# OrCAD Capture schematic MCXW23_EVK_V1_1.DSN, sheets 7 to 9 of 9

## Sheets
7 07_Current_Measurement: size A2
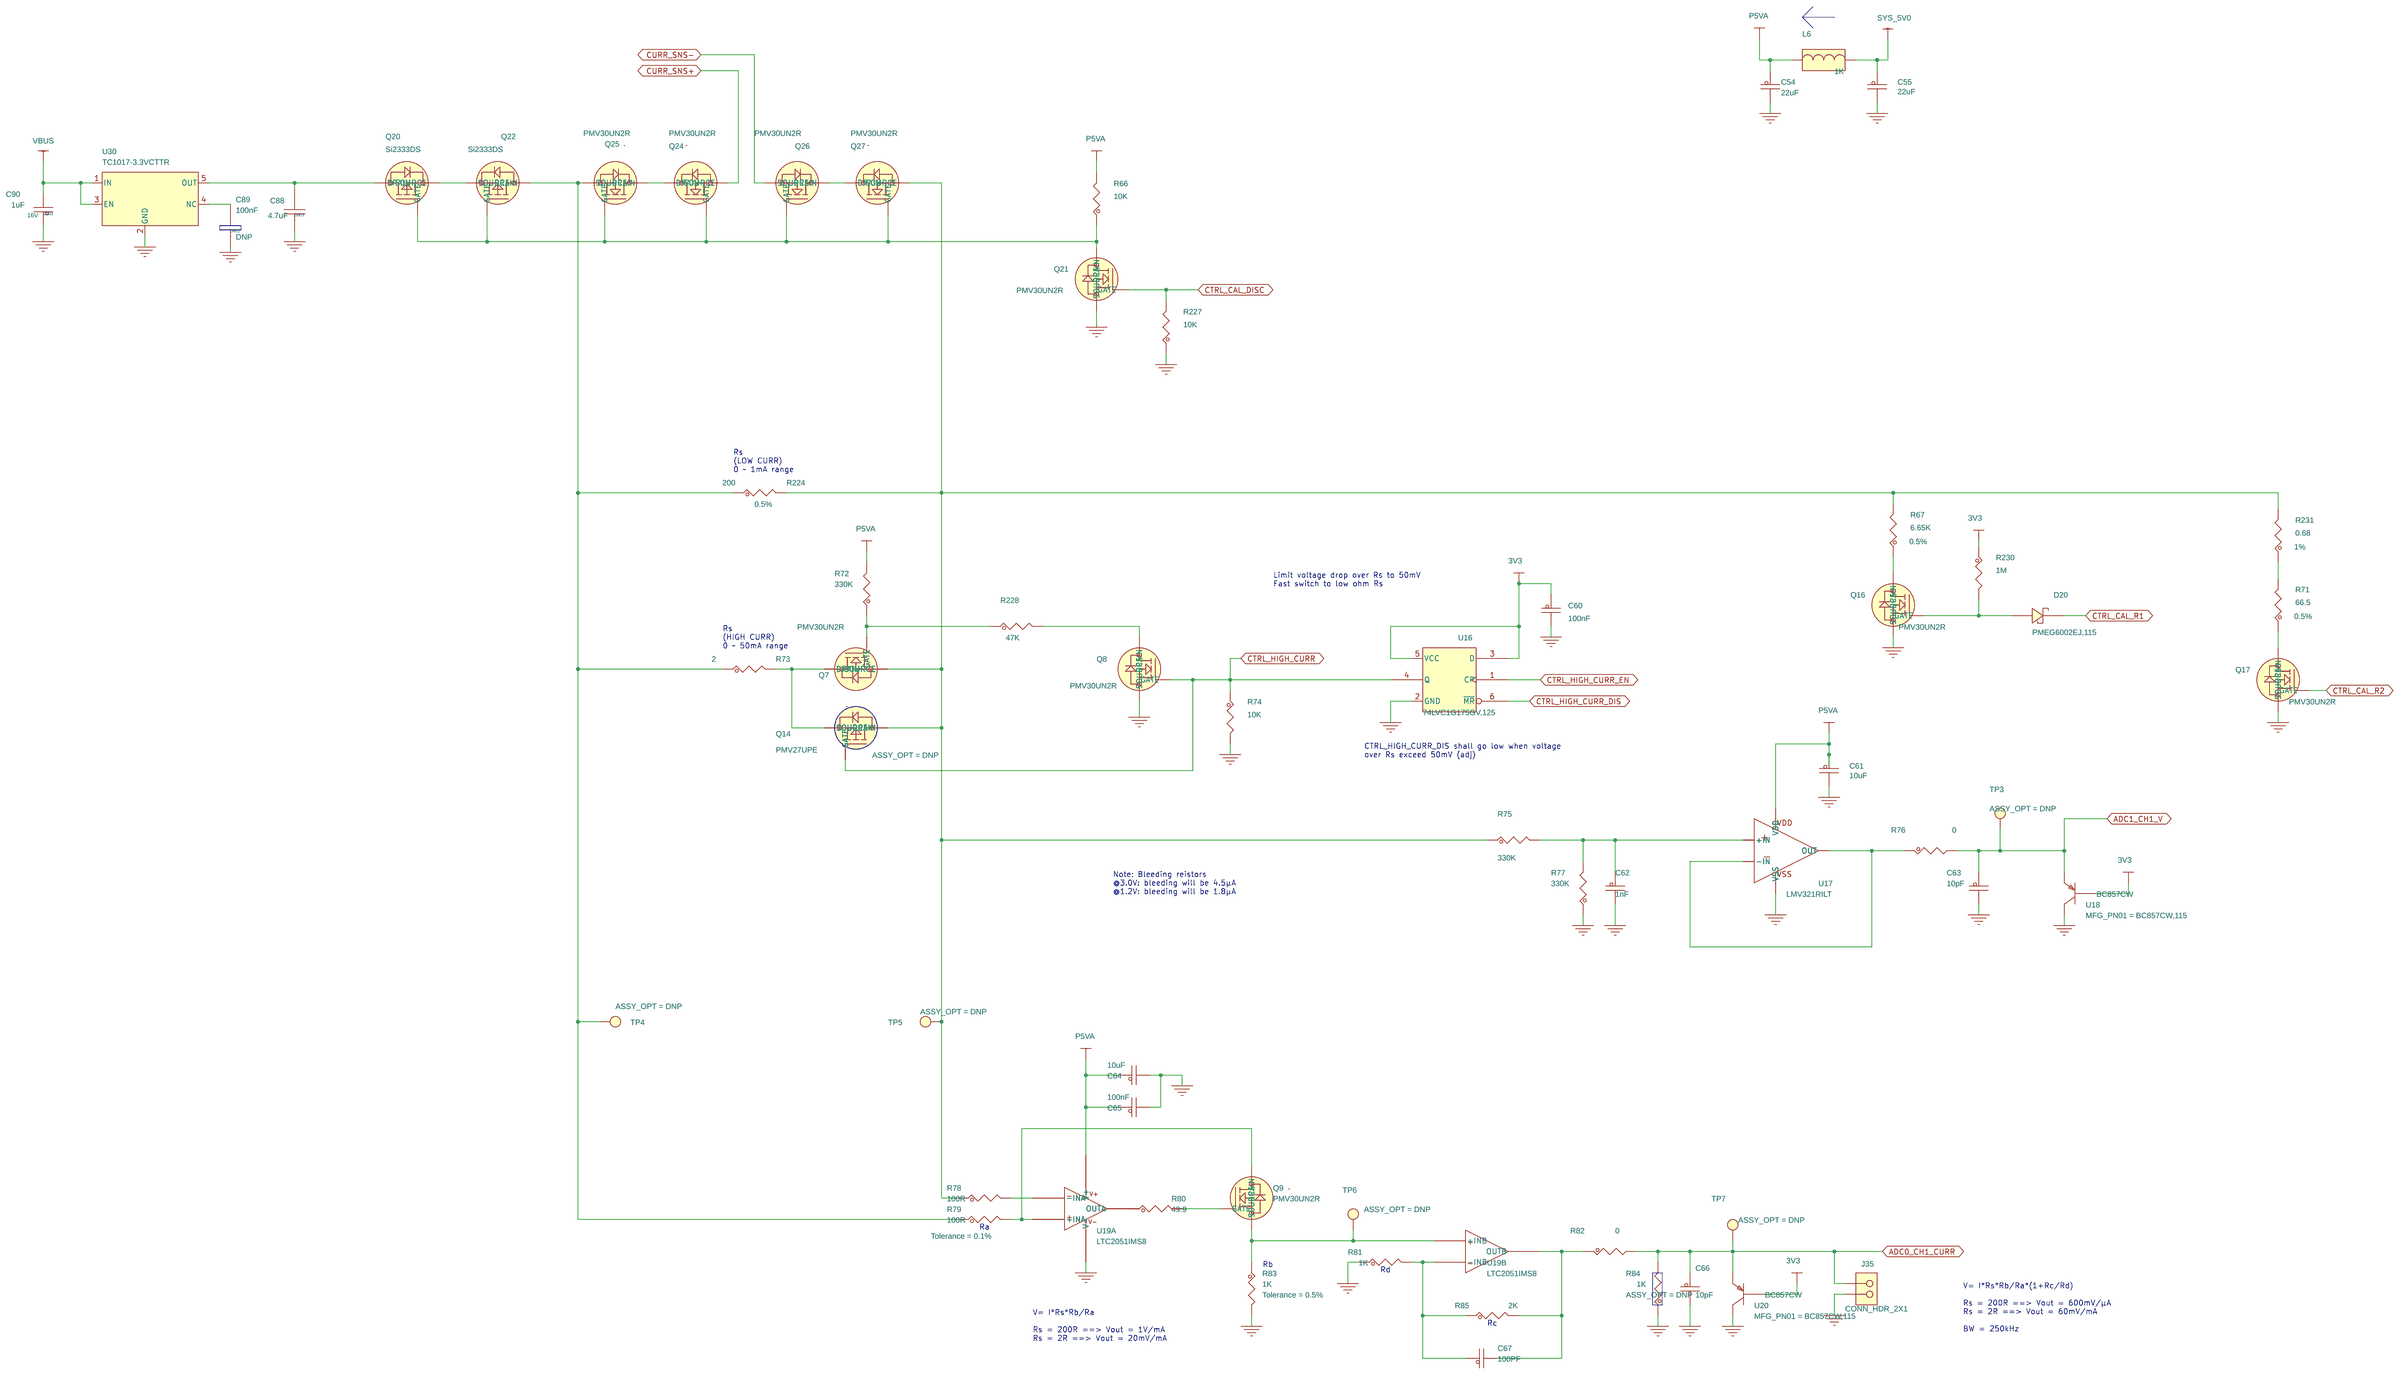
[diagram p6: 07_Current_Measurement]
8 08_MCU Link ISP: size A3
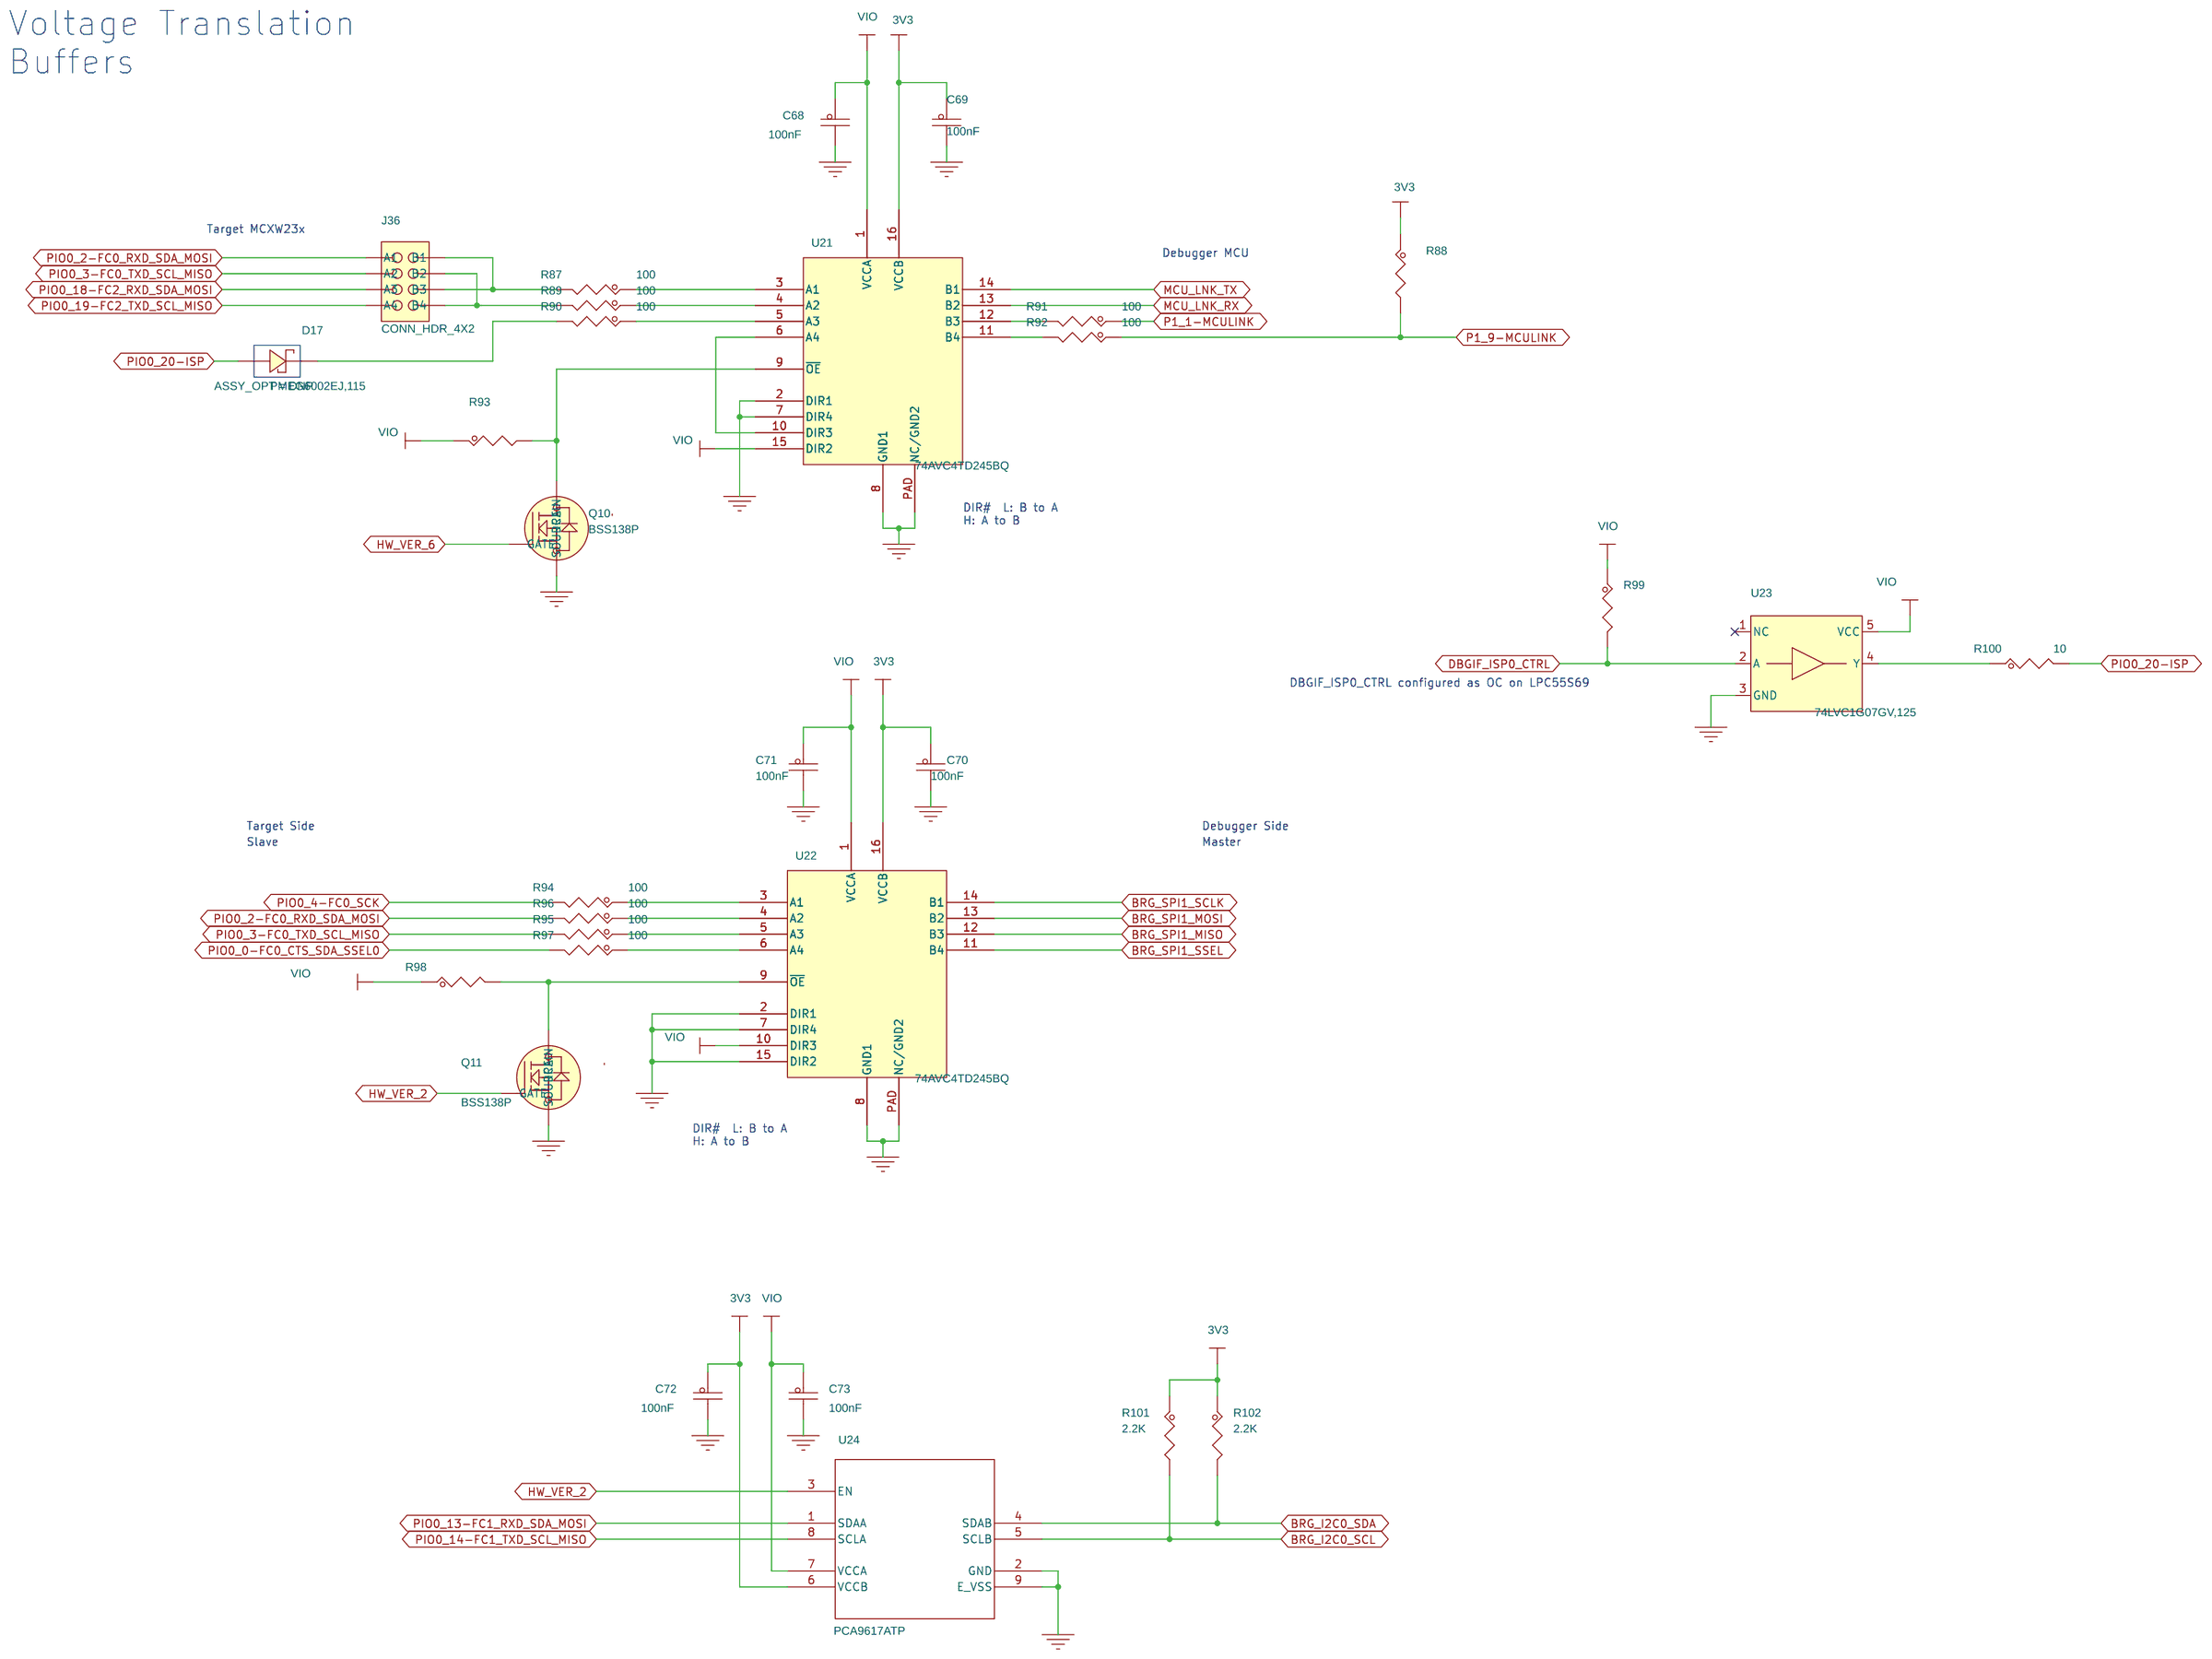
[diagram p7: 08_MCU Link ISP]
9 09_MCU Link SWD: size A3
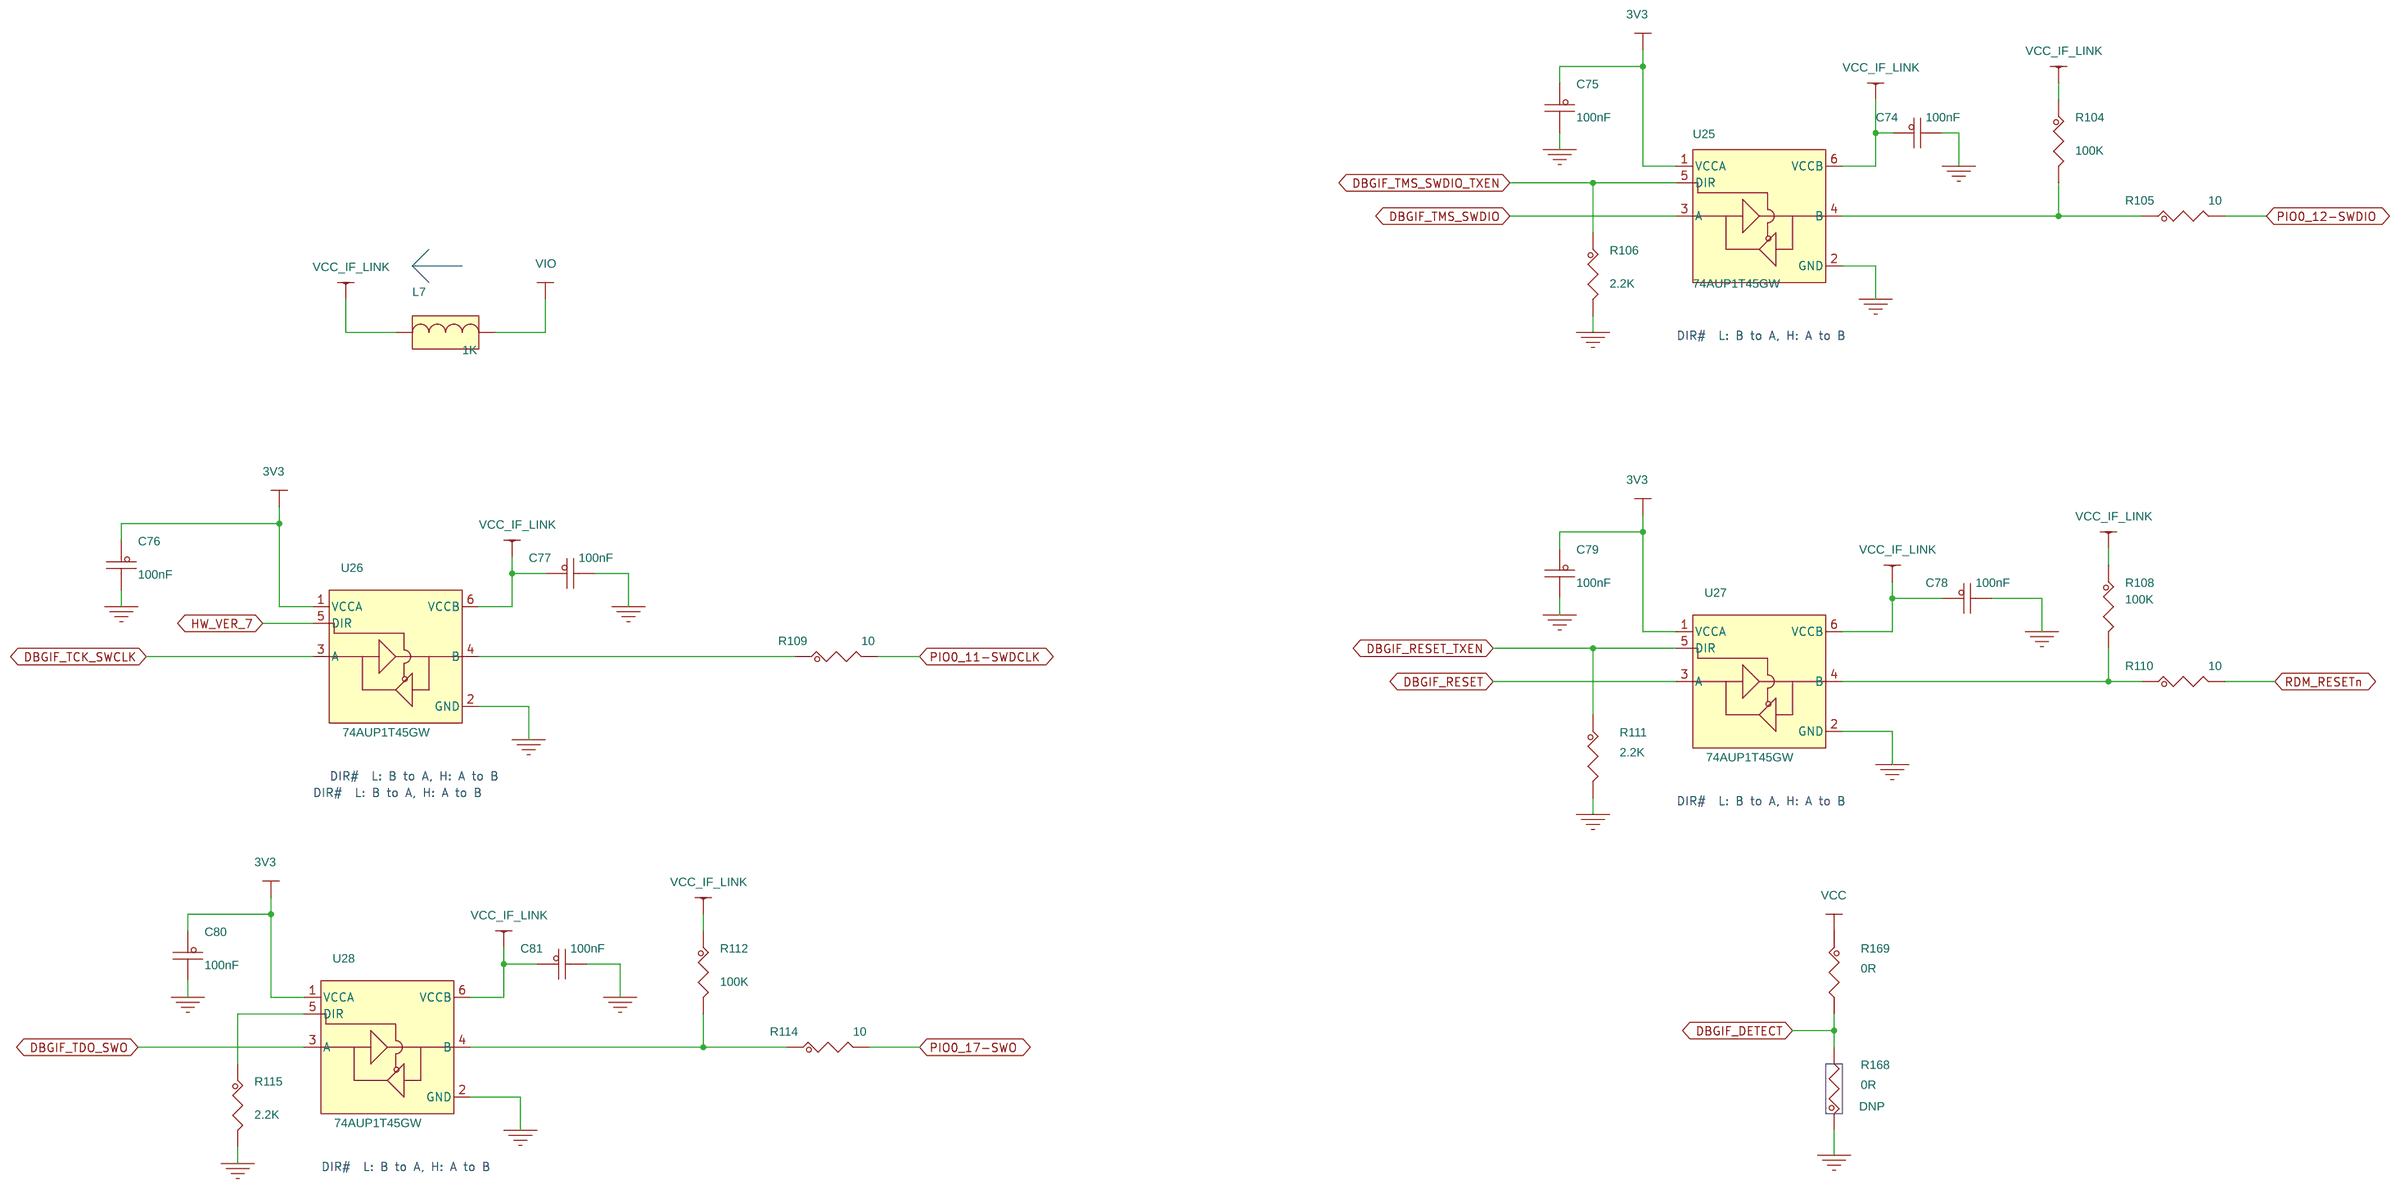
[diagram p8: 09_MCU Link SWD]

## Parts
sheet 07_Current_Measurement
C54  22uF  [CC0603_OV]
C55  22uF  [CC0603_OV]
C60  100nF  [CC0402_25]
C61  10uF  [CC0603_OV]
C62  1nF  [CC0402_25]
C63  10pF  [CC0402_25]
C64  10uF  [CC0603_OV]
C65  100nF  [CC0402_25]
C66  10pF  [CC0402_25]
C67  100PF  [CC0603_OV]
C88  4.7uF  [CC0603_OV]
C89  100nF  [CC0402_25]
C90  1uF  [CC0603_OV]
D20  PMEG6002EJ,115  [SOD323F-R]
J35  CONN_HDR_2X1  [HE14-2X1PTS-MD]
L6  1K  [murata-blm15]
Q7  PMV30UN2R  [SOT23_GSD]
Q8  PMV30UN2R  [SOT23_GSD]
Q9  PMV30UN2R  [SOT23_GSD]
Q14  PMV27UPE  [SOT23_GSD]
Q16  PMV30UN2R  [SOT23_GSD]
Q17  PMV30UN2R  [SOT23_GSD]
Q20  Si2333DS  [SOT23_GSD]
Q21  PMV30UN2R  [SOT23_GSD]
Q22  Si2333DS  [SOT23_GSD]
Q24  PMV30UN2R  [SOT23_GSD]
Q25  PMV30UN2R  [SOT23_GSD]
Q26  PMV30UN2R  [SOT23_GSD]
Q27  PMV30UN2R  [SOT23_GSD]
R66  10K  [RC0402_25]
R67  6.65K  [RC0603_OV]
R71  66.5  [RC0603_OV]
R72  330K  [RC0402_25]
R73  2  [RC0603_OV]
R74  10K  [RC0402_25]
R75  330K  [RC0402_25]
R76  0  [RC0603_OV]
R77  330K  [RC0402_25]
R78  100R  [RC0402_25]
R79  100R  [RC0402_25]
R80  49.9  [RC0402_25]
R81  1K  [RC0402_25]
R82  0  [RC0603_OV]
R83  1K  [RC0402_25]
R84  1K  [RC0402_25]
R85  2K  [RC0603_OV]
R224  200  [RC0603_OV]
R227  10K  [RC0402_25]
R228  47K  [RC0402_25]
R230  1M  [RC0402_25]
R231  0.68  [RC0603_OV]
TP3  TPAD_050  [TPAD_050]
TP4  TPAD_050  [TPAD_050]
TP5  TPAD_050  [TPAD_050]
TP6  TPAD_050  [TPAD_050]
TP7  TPAD_050  [TPAD_050]
U16  74LVC1G175GV,125  [SOT457]
U17  LMV321RILT  [sot23-5-R]
U18  BC857CW  [SC70-BEC]
U19  LTC2051IMS8  [MSOP8_MS]  (sections A,B)
U20  BC857CW  [SC70-BEC]
U30  TC1017-3.3VCTTR  [SOT23-5-R]
sheet 08_MCU Link ISP
C68  100nF  [CC0402_25]
C69  100nF  [CC0402_25]
C70  100nF  [CC0402_25]
C71  100nF  [CC0402_25]
C72  100nF  [CC0402_25]
C73  100nF  [CC0402_25]
D17  PMEG6002EJ,115  [SOD323F-R]
J36  CONN_HDR_4X2  [HE14-2X4PTS-MD]
Q10  BSS138P  [SOT23_GSD]
Q11  BSS138P  [SOT23_GSD]
R87  100  [RC0402_25]
R88  10K  [RC0402_25]
R89  100  [RC0402_25]
R90  100  [RC0402_25]
R91  100  [RC0402_25]
R92  100  [RC0402_25]
R93  10K  [RC0402_25]
R94  100  [RC0402_25]
R95  100  [RC0402_25]
R96  100  [RC0402_25]
R97  100  [RC0402_25]
R98  10K  [RC0402_25]
R99  10K  [RC0402_25]
R100  10  [RC0402_25]
R101  2.2K  [RC0402_25]
R102  2.2K  [RC0402_25]
U21  74AVC4TD245BQ  [DHVQFN16]
U22  74AVC4TD245BQ  [DHVQFN16]
U23  74LVC1G07GV,125  [SOT753]
U24  PCA9617ATP  [HWSON8]
sheet 09_MCU Link SWD
C74  100nF  [CC0402_25]
C75  100nF  [CC0402_25]
C76  100nF  [CC0402_25]
C77  100nF  [CC0402_25]
C78  100nF  [CC0402_25]
C79  100nF  [CC0402_25]
C80  100nF  [CC0402_25]
C81  100nF  [CC0402_25]
L7  1K  [murata-blm15]
R104  100K  [RC0402_25]
R105  10  [RC0402_25]
R106  2.2K  [RC0402_25]
R108  100K  [RC0402_25]
R109  10  [RC0402_25]
R110  10  [RC0402_25]
R111  2.2K  [RC0402_25]
R112  100K  [RC0402_25]
R114  10  [RC0402_25]
R115  2.2K  [RC0402_25]
R168  0R  [RC0603_OV]
R169  0R  [RC0603_OV]
U25  74AUP1T45GW  [sot363]
U26  74AUP1T45GW  [sot363]
U27  74AUP1T45GW  [sot363]
U28  74AUP1T45GW  [sot363]

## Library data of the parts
C54 C55 = CAP_NP: CAP CER 22uF 10V 20% X5R 0603; AGILE_PN: 150-79530; CAD_APPROVED: Yes; FPLIST: CC0603_OV,CC0603; HEIGHT: 1MM; MFG_NAME01: TDK; MFG_PN01: C1608X5R1A226M080AC; Manufacturer: TDK; Manufacturer PN: C1608X5R1A226M080AC; Package Size: 0603; ROHS: Yes; Tolerance: 20%; VOLTAGE: 10V
C60 C65 C68-C73 C75-C81 = CAP_NP: CAP CER 0.1UF 25V X7R 0402; FPLIST: CC0402_25,CC0402_HD,0402_CC; HEIGHT: 0.55MM; MFG_NAME01: TDK; MFG_PN01: CGA2B3X7R1E104K050BB; Manufacturer: TDK; Manufacturer PN: CGA2B3X7R1E104K050BB; Package Size: 0402; Package Type: SMD; ROHS: Yes; TYPE: 0402; Tolerance: 10%; VOLTAGE: 25V
C61 C64 = CAP_NP: SMD Multilayer Ceramic Capacitor, 10 µF, 10 V, 0603, ± 20%, X5R; CAD_APPROVED: Yes; FPLIST: CC0603_OV,CC0603; Farnell: 2113070; HEIGHT: 1MM; MFG_NAME01: Taiyo Yuden; MFG_PN01: LMK107BBJ106MALT; Manufacturer: Taiyo Yuden; Manufacturer PN: LMK107BBJ106MALT; Package Size: 0603; ROHS: Yes; Tolerance: 20%; VOLTAGE: 10V
C62 = CAP_NP: CAP CER 0.001uF 50V 10% X7R 0402; AGILE_PN: 150-80278; CAD_APPROVED: Yes; FPLIST: CC0402_25,CC0402_HD,0402_CC; HEIGHT: 0.6MM; MFG_NAME01: VISHAY INTERTECHNOLOGY; MFG_PN01: VJ0402Y102KXAAC; Manufacturer: VISHAY INTERTECHNOLOGY; Manufacturer PN: VJ0402Y102KXAAC; Package Size: 0402; Package Type: SMD; ROHS: Yes; Temp Range: -55°C to +150°C; Tolerance: 10%; VOLTAGE: 50V
C63 C66 = CAP_NP: CAP CER 10pF 50V 2% C0G 0402; AGILE_PN: 150-78893; CAD_APPROVED: Yes; FPLIST: CC0402_25,CC0402_HD,0402_CC; HEIGHT: 0.55 MM; MFG_NAME01: MURATA; MFG_PN01: GJM1555C1H100GB01D; Manufacturer: MURATA; Manufacturer PN: GJM1555C1H100GB01D; Package Size: 0402; Package Type: 180mm Paper Tape; ROHS: Yes; Temp Range: -55°C to +125°C; Tolerance: 2%; VOLTAGE: 50V
C67 = CAP_NP: CAP CER 100pF 100V 5% C0G 0603; AGILE_PN: 150-80505; CAD_APPROVED: Yes; FPLIST: CC0603_OV,CC0603,0603_CC; HEIGHT: 0.87MM; MFG_NAME01: WURTH ELEKTRONIK EISOS GMBH & CO. KG (ELECTRONIC & ELECTROMEHANICAL COMP); MFG_PN01: 885012006079; Manufacturer: WURTH ELEKTRONIK EISOS GMBH & CO. KG (ELECTRONIC & ELECTROMEHANICAL COMP); Manufacturer PN: 885012006079; ROHS: Yes; Temp Range: -55°C ~ 125°C
C88 = CAPACITOR__0: SMD Multilayer Ceramic Capacitor, 4.7 µF, 16 V, ± 10%, X5R; CAD_APPROVED: Yes; CLASS: DISCRETE; FPLIST: CC0603_OV,CC0603; Farnell: 3581438; HEIGHT: 1MM; MFG_NAME01: MURATA; MFG_PN01: GRT188R61C475KE13D; Manufacturer: MURATA; Manufacturer PN: GRT188R61C475KE13D; PUISS/VOLT: 10V; Package Size: 0603; TYPE: 0603; VOLTAGE: 16V
C89 = CAPACITOR__0: CAP CER 0.1UF 25V X7R 0402; ASSY_OPT: DNP; Assembly Option: DNP; CLASS: DISCRETE; FPLIST: CC0402_25,CC0402_HD,0402_CC; HEIGHT: 0.55MM; MFG_NAME01: TDK; MFG_PN01: CGA2B3X7R1E104K050BB; Manufacturer: TDK; Manufacturer PN: CGA2B3X7R1E104K050BB; Package Size: 0402; Package Type: SMD; ROHS: Yes; TOLERANCE: 10%; TYPE: 0402; VOLTAGE: 25V
C90 = CAP_NP: CAP CER 1UF 16V X5R 0603; Distributor: Digi-Key; Distributor PN: 490-1536-6-ND; MFG_NAME01: Murata Electronics North America; MFG_PN01: GRM188R61C105KA93D; Manufacturer: Murata Electronics North America; Manufacturer PN: GRM188R61C105KA93D; OrderCode: FARNELL 1907343; PUISS/VOLT: 16V; STUFFING: YES; Type: 0603; Datasheet: http://www.murata.com/~/media/webrenewal/support/library/catalog/products/capacitor/mlcc/c02e.ashx
D20 = DIODE_SCHTKY: Schottky Rectifier, Low VF, 60 V, 200 mA, Single, SOD-323F, 2 Pins, 600 mV; Farnell: 1972726; MFG_NAME01: Nexperia USA Inc.; Manufacturer: Nexperia USA Inc.; Datasheet: https://assets.nexperia.com/documents/data-sheet/PMEG6002EJ.pdf
J35 = CONN_HDR_2X1
L6 = BEAD: IND FER BEAD 1K@100MHz 250mA 25% 0402; AGILE_PN: 180-78847; CAD_APPROVED: Yes; FPLIST: IND_0402,0402_CC; Farnell: 1515785; HEIGHT: 0.55MM; MFG_NAME01: MURATA; MFG_PN01: BLM15HD102SN1; Manufacturer: MURATA; Manufacturer PN: BLM15HD102SN1; ROHS: Yes; Temp Range: -55&#8451; to 125&#8451;
Q7-Q9 Q16 Q17 Q21 Q24-Q27 = MOSFET_N_0: Power MOSFET, N Channel, 20 V, 5.4 A, 0.024 ohm, SOT-23, Surface Mount; CAD_APPROVED: Yes; Farnell: 2469652; HEIGHT: 3.0MM; MFG_NAME01: NEXPERIA; Manufacturer: NEXPERIA; ROHS: Yes; Temp Range: -65°C ~ 150°C; Temp_Range: -65°C ~ 150°C; VOLTAGE: 20V
Q14 = MOSFET_P_0: TRAN PMOS 20V 4.5A SOT23-3; AGILE_PN: 480-80187; ASSY_OPT: DNP; Assembly Option: DNP; CAD_APPROVED: Yes; HEIGHT: 1.1 MM; MFG_NAME01: Nexperia; MFG_PN01: PMV27UPER; Manufacturer: Nexperia; Manufacturer PN: PMV27UPER; Package Size: 1.4x3x1.1MM; ROHS: Yes; Rated Power: 490mW (Ta), 4.15W (Tc)
Q20 = MOSFET_P_0: MOSFET 12V 5.3A 1.25W 32mohm @ 4.5V; AGILE_PN: 480-80187; CAD_APPROVED: Yes; Farnell: 1867182; HEIGHT: 1.1 MM; MFG_NAME01: Vishay; Manufacturer: Vishay; Mouser: 781-SI2333DS-GE3; Package Size: 1.4x3x1.1MM; ROHS: Yes; Rated Power: 490mW (Ta), 4.15W (Tc)
Q22 = MOSFET_P_0: MOSFET 12V 5.3A 1.25W 32mohm @ 4.5V; AGILE_PN: 480-80187; CAD_APPROVED: Yes; Farnell: 1867182; HEIGHT: 1.1 MM; MFG_NAME01: Vishay; MFG_PN01: PMV27UPER; Manufacturer: Vishay; Manufacturer PN: PMV27UPER; Mouser: 781-SI2333DS-GE3; Package Size: 1.4x3x1.1MM; ROHS: Yes; Rated Power: 490mW (Ta), 4.15W (Tc)
R66 R74 R227 = RES: RES MF 10K 1/16W 1% 0402; AGILE_PN: 470-80452; CAD_APPROVED: Yes; FPLIST: RC0402_25,RC0402_HD,0402_CC; HEIGHT: 0.40 MM; MFG_NAME01: NIC COMPONENTS CORP; MFG_PN01: NRCL04F1002TRF; Manufacturer: NIC COMPONENTS CORP; Manufacturer PN: NRCL04F1002TRF; ROHS: Yes; Tolerance: 1%
R67 = RES: RES MF 6.65K 1/10W 1% AEC-Q200 0603; AGILE_PN: 470-81749; CAD_APPROVED: Yes; Digikey: 311-2659-2-ND; FPLIST: RC0603_OV,RC0603,0603_CC; HEIGHT: 0.55MM; MFG_NAME01: YAGEO; MFG_PN01: RT0603DRE076K65L; Manufacturer: YAGEO; Manufacturer PN: RT0603DRE076K65L; ROHS: Yes; Temp Range: -55C to +155C; Tolerance: 0.5%
R71 = RES: RES SMD 66.5OHM 0.5% 1/10W 0603; CAD_APPROVED: Yes; Digikey: YAG1713CT-ND; FPLIST: RC0603_OV,RC0603,0603_CC; MFG_NAME01: YAGEO; MFG_PN01: RT0603BRD0766R5L; Manufacturer: YAGEO; Manufacturer PN: RT0603BRD0766R5L; ROHS: Yes; Temp Range: -55C to +155C; Tolerance: 0.5%
R72 R75 R77 = RES: RES MF 330K  1/16W 1% 0402; AGILE_PN: 470-31117; CAD_APPROVED: Yes; FPLIST: RC0402_25,RC0402_HD,0402_CC; HEIGHT: 0.40 MM; MFG_NAME01: YAGEO AMERICA; MFG_PN01: RC0402FR-07330KL; Manufacturer: YAGEO AMERICA; Manufacturer PN: RC0402FR-07330KL; ROHS: Yes; Temp Range: -55°C ~ 155°C; Tolerance: 1%; VOLTAGE: 50V
R73 = RES: RES 0603 2R0 0.1% 25PPM 1K RL; AGILE_PN: 470-82171; CAD_APPROVED: Yes; Digikey: 1712-CPF0603B2R0E1CT-ND; FPLIST: RC0603_OV,RC0603,0603_CC; HEIGHT: 0.55MM; MFG_NAME01: ROHM; MFG_PN01: ESR10EZPF2R00; Manufacturer: ROHM; Manufacturer PN: ESR10EZPF2R00; ROHS: Yes; Temp Range: -55°C ~ 155°C; Tolerance: 0.5%
R76 R82 = RES: RES MF ZERO OHM 1/10W -- 0603; AGILE_PN: 470-80866; CAD_APPROVED: Yes; FPLIST: RC0603_OV,RC0603,R603-X2,0603_CC; HEIGHT: 0.6MM; MFG_NAME01: YAGEO AMERICA; MFG_PN01: RC0603FR-070RL; Manufacturer: YAGEO AMERICA; Manufacturer PN: RC0603FR-070RL; ROHS: Yes; Temp Range: –55 °C to +155 °C
R78 R79 = RES: RES MF 100 OHM 1/16W 0.1% AEC-Q200 0402; AGILE_PN: 470-30279; CAD_APPROVED: Yes; FPLIST: RC0402_25,RC0402_HD,0402_CC; HEIGHT: 0.4MM; MFG_NAME01: VISHAY INTERTECHNOLOGY; MFG_PN01: MCS04020D1000BE100; Manufacturer: VISHAY INTERTECHNOLOGY; Manufacturer PN: MCS04020D1000BE100; ROHS: Yes; Tolerance: 0.1%
R80 = RES: RES 49.9 OHM 1/16W 0.1% AEC-Q200 0402; AGILE_PN: 470-76559; CAD_APPROVED: Yes; FPLIST: RC0402_25,RC0402_HD,0402_CC; HEIGHT: 0.4mm; MFG_NAME01: SUSUMU CO. LTD.; MFG_PN01: RG1005P-49R9-B; Manufacturer: SUSUMU CO. LTD.; Manufacturer PN: RG1005P-49R9-B; ROHS: Yes; Tolerance: 0.1%; VOLTAGE: 25V
R81 R83 = RES: RES MF 1K 1/16W 0.5% 0402; AGILE_PN: 470-80057; CAD_APPROVED: Yes; FPLIST: RC0402_25,RC0402_HD,0402_CC; HEIGHT: 0.4MM; MFG_NAME01: PANASONIC; MFG_PN01: ERA2AED102X; Manufacturer: PANASONIC; Manufacturer PN: ERA2AED102X; ROHS: Yes; Tolerance: 0.5%
R84 = RES: RES MF 1K 1/16W 0.5% 0402; AGILE_PN: 470-80057; ASSY_OPT: DNP; Assembly Option: DNP; CAD_APPROVED: Yes; FPLIST: RC0402_25,RC0402_HD,0402_CC; HEIGHT: 0.4MM; MFG_NAME01: PANASONIC; MFG_PN01: ERA2AED102X; Manufacturer: PANASONIC; Manufacturer PN: ERA2AED102X; ROHS: Yes; Tolerance: 0.5%
R85 = RES: RES MF 2K 1/10W 1% 0603; AGILE_PN: 470-81379; CAD_APPROVED: Yes; FPLIST: RC0603_OV,RC0603,0603_CC; HEIGHT: 0.55MM; MFG_NAME01: YAGEO; MFG_PN01: RC0603FR-072KL; Manufacturer: YAGEO; Manufacturer PN: RC0603FR-072KL; ROHS: Yes; Temp Range: -55°C to +155°C; Tolerance: 1%
R224 = RES: RES MF 200 OHM 1/8W 0.5% 0603; AGILE_PN: 470-81343; CAD_APPROVED: Yes; FPLIST: RC0603_OV,RC0603,0603_CC; Farnell: 3579762; HEIGHT: 0.55MM; MFG_NAME01: Panasonic; MFG_PN01: ERJUP3D2000V; Manufacturer: Panasonic; Manufacturer PN: ERJUP3D2000V; ROHS: Yes; Temp Range: -55°C to +155°C; Tolerance: 0.5%
R228 = RES: SMD Chip Resistor, 47 kohm, ± 1%, 62.5 mW, 0402 [1005 Metric], Thick Film, General Purpose; CAD_APPROVED: Yes; FPLIST: RC0402_25,RC0402_HD,0402_CC; HEIGHT: 0.40 MM; MFG_NAME01: YAGEO AMERICA; MFG_PN01: RC0402FR-0747KL; Manufacturer: YAGEO AMERICA; Manufacturer PN: RC0402FR-0747KL; ROHS: Yes; Temp Range: -55°C ~ 155°C; Tolerance: 1%; VOLTAGE: 50V
R230 = RES: RES MF 1M 1/16W 1% 0402; CAD_APPROVED: Yes; FPLIST: RC0402_25,RC0402_HD,0402_CC; HEIGHT: 0.40 MM; MFG_PN01: AC0402FR-071ML; Manufacturer PN: AC0402FR-071ML; ROHS: Yes; Tolerance: 1%
R231 = RES: RES SMD 0.68OHM 1% 1/10W 0603; CAD_APPROVED: Yes; FPLIST: RC0603_OV,RC0603,0603_CC; MFG_NAME01: PANASONIC; MFG_PN01: ERJ3BQFR68V; Manufacturer: PANASONIC; Manufacturer PN: ERJ3BQFR68V; ROHS: Yes; Temp Range: -55C to +155C; Tolerance: 1%
TP3-TP7 = TEST_POINT_L: TEST POINT PAD 50MIL DIA SMT, NO PART TO ORDER; AGILE_PN: 211-76644; ASSY_OPT: DNP; Assembly Option: DNP; CAD_APPROVED: Yes; EN: 666-1-00186; HEIGHT: 0.1MM; KEY Number: 666-1-00186@1; MFG_NAME01: NOTACOMPONENT; MFG_PN01: NOTACOMPONENT; Manufacturer: NOTACOMPONENT; Manufacturer PN: NOTACOMPONENT; Mfg: NA; Mfg Part No: 666-1-00186; ROHS: Yes
U16 = 1_D_FLIPFLOP_6P: IC FLIP-FLOP SINGLE D-TYPE 1.65-5.5V SOT363; AGILE_PN: 312-82400; CAD_APPROVED: YES; Farnell: 2445063; HEIGHT: 1.1 MM; MFG_NAME01: Nexperia USA Inc.; Manufacturer: Nexperia USA Inc.; Package Size: SC-74, SOT-457; ROHS: YES; Supply Voltage: 1.65V ~ 5.5V
U17 = OPAMP_SGL_5P: Operational Amplifier, Single, 1 Amplifier, 1.3 MHz, 0.45 V/µs, 2.7V to 6V, SOT-23, 5 Pins; 3D_Mechanical_Footprint_File: sot23-5; AGILE_PN: 315-81237; CAD_APPROVED: Yes; Farnell: 1374134; HEIGHT: 1.45MM; MFG_NAME01: STMicroelectronics; Manufacturer: STMicroelectronics; ROHS: Yes; Temp Range: -40C to 125C; VOLTAGE: 2.7-6V
U18 U20 = PNP_0: TRAN PNP GEN 100mA 45V AEC-Q101 SC70; AGILE_PN: 480-80464; CAD_APPROVED: YES; Farnell: 1907655; HEIGHT: 1.1 MM; MFG_NAME01: Nexperia USA Inc.; MFG_PN01: BC857CW,115; Manufacturer: Nexperia USA Inc.; Manufacturer PN: BC857CW,115; Package Size: SC-70, SOT-323; ROHS: YES; Rated Power: 200mW; Temp Range: -65°C to +150°C
U19 = OPAMP_DUAL_8P_B: IC LIN OPAMP DUAL 2.7-5.5V MSOP8; AGILE_PN: 315-80868; CAD_APPROVED: Yes; HEIGHT: 1.1MM; MFG_NAME01: ANALOG DEVICES; MFG_PN01: LTC2051IMS8#PBF; Manufacturer: ANALOG DEVICES; Manufacturer PN: LTC2051IMS8#PBF; Mouser: 584-LTC2051IMS8#PBF; Package Size: MSOP-8; ROHS: Yes; VOLTAGE: 2.7-5.5V
U30 = TPS76930_1: Fixed LDO Voltage Regulator, 2.7V to 6V, 285mV Dropout, 3.3Vout, 150mAout, SOT-23-5; Distributor: Digi-Key; Farnell: 1331509; Manufacturer: Microchip; STUFFING: YES; Supplier: Digikey; Datasheet: https://www.farnell.com/datasheets/2124733.pdf
D17 = DIODE_SCHTKY: Schottky Rectifier, Low VF, 60 V, 200 mA, Single, SOD-323F, 2 Pins, 600 mV; ASSY_OPT: DNP; Assembly Option: DNP; Farnell: 1972726; MFG_NAME01: Nexperia USA Inc.; Manufacturer: Nexperia USA Inc.; Datasheet: https://assets.nexperia.com/documents/data-sheet/PMEG6002EJ.pdf
J36 = CONN_HDR_4X2: Pin Header, Board-to-Board, 2.54 mm, 2 Rows, 8 Contacts, Through Hole, AMPMODU II; Farnell: 3398641; MFG_NAME01: AMP - TE CONNECTIVITY; MFG_PN01: 826656-4; Manufacturer: AMP - TE CONNECTIVITY; Manufacturer PN: 826656-4
Q10 Q11 = MOSFET_N_0: TRAN NMOS 60V 360MA AEC-Q101 TO-236AB; AGILE_PN: 480-79842; CAD_APPROVED: Yes; Farnell: 1859849; HEIGHT: 1.1MM; MFG_NAME01: NEXPERIA; MFG_PN01: BSS138P,215; Manufacturer: NEXPERIA; Manufacturer PN: BSS138P,215; ROHS: Yes; Temp Range: -65°C ~ 150°C; Temp_Range: -65°C ~ 150°C; VOLTAGE: 60V
R87 R89-R92 R94-R97 = RES: RES MF 100 OHM 1/16W 5% 0402; AGILE_PN: 470-75591; CAD_APPROVED: Yes; FPLIST: RC0402_25,RC0402_HD,RC0402_X2,0402_CC; HEIGHT: 0.45mm; MFG_NAME01: PANASONIC; MFG_PN01: ERJ2GEJ101X; Manufacturer: PANASONIC; Manufacturer PN: ERJ2GEJ101X; ROHS: Yes; Tolerance: 5%
R88 R93 R98 = RES: RES MF 10K 1/16W 5% 0402; AGILE_PN: 470-75557; CAD_APPROVED: Yes; FPLIST: RC0402_25,RC0402_HD,0402_CC; HEIGHT: 0.4 MM; MFG_NAME01: VISHAY INTERTECHNOLOGY; MFG_PN01: CRCW040210K0JNED; Manufacturer: VISHAY INTERTECHNOLOGY; Manufacturer PN: CRCW040210K0JNED; ROHS: Yes; TOL: 5%; Tolerance: 5%
R99 = RES: RES MF 10K 1/16W 5% 0402; AGILE_PN: 470-75557; CAD_APPROVED: Yes; FPLIST: RC0402_25,RC0402_HD,0402_CC; HEIGHT: 0.4 MM; MFG_NAME01: VISHAY INTERTECHNOLOGY; MFG_PN01: CRCW040210K0JNED; Manufacturer: VISHAY INTERTECHNOLOGY; Manufacturer PN: CRCW040210K0JNED; ROHS: Yes; Tolerance: 5%
R100 R105 R109 R110 R114 = RES: RES MF 10 OHM 1/16W 1% AEC-Q200 0402; AGILE_PN: 470-80978; CAD_APPROVED: Yes; FPLIST: RC0402_25,RC0402_HD,0402_CC; HEIGHT: 0.4MM; MFG_NAME01: KOA SPEER; MFG_PN01: RK73H1ETTP10R0F; Manufacturer: KOA SPEER; Manufacturer PN: RK73H1ETTP10R0F; ROHS: Yes; Temp Range: –55 °C to +155 °C; Tolerance: 1%
R101 R102 R106 R111 R115 = RES: RES MF 2.2K 1/16W 1% 0402; AGILE_PN: 470-78359; CAD_APPROVED: Yes; FPLIST: RC0402_25,RC0402_HD,0402_CC; HEIGHT: 0.4MM; MFG_NAME01: WALSIN TECHNOLOGY CORP.; MFG_PN01: WR04X2201FTL; Manufacturer: WALSIN TECHNOLOGY CORP.; Manufacturer PN: WR04X2201FTL; ROHS: Yes; Temp Range: -55C to +155C; Temp_Range: -55C to +155C; Tolerance: 1%
U21 U22 = 74AVC4TD245BQ_DHVQFN16_1: IC DUAL SUPPLY XCVR XLTR 4BIT 0-3.6V DHVQFN16; 3D_Mechanical_Footprint_File: ftp://fcl.am.freescale.net/ALLEGRO/step/dhvqfn16_0p5_3p6x2p6.STEP; AGILE_PN: 312-81329; CAD_APPROVED: Yes; Farnell: 3441770; HEIGHT: 1MM; MFG_NAME01: NEXPERIA; MFG_PN01: 74AVC4TD245BQ,115; Manufacturer: NEXPERIA; Manufacturer PN: 74AVC4TD245BQ,115; Mouser: 771-74AVC4TD245BQ115; ROHS: Yes
U23 = 74AUP1G07GW: IC BUF NON-INV SGL 1.65-5.5V AEC-Q100 TSSOP5; AGILE_PN: 312-82179; CAD_APPROVED: Yes; Farnell: 2463746; HEIGHT: 1.1MM; MFG_NAME01: NEXPERIA; Manufacturer: NEXPERIA; ROHS: Yes; Temp Range: -40 to +125C; VOLTAGE: 1.65-5.5V
U24 = PCA9617ATP: IC LEVEL TRANSLATOR FM+ I2C 0.8-5.5V HWSON8; AGILE_PN: 312-82381; CAD_APPROVED: YES; Farnell: 2400487; HEIGHT: 0.8 MM; MFG_NAME01: NXP SEMICONDUCTORS; MFG_PN01: PCA9617ATPZ; Manufacturer: NXP SEMICONDUCTORS; Manufacturer PN: PCA9617ATPZ; ROHS: Yes; Supply Voltage: 0.8-5.5V; VOLTAGE: 0.8-5.5V
C74 = CAP_NP: CAP CER 0.1UF 25V X7R 0402; FPLIST: CC0402_25,CC0402_HD,0402_CC; HEIGHT: 0.55MM; MFG_NAME01: TDK; MFG_PN01: CGA2B3X7R1E104K050BB; Manufacturer: TDK; Manufacturer PN: CGA2B3X7R1E104K050BB; Package Size: 0402; Package Type: SMD; ROHS: Yes; Tolerance: 10%; VOLTAGE: 25V
L7 = BEAD: IND FER BEAD 1K@100MHz 250mA 25% 0402; AGILE_PN: 180-78847; CAD_APPROVED: Yes; FPLIST: IND_0402,0402_CC; HEIGHT: 0.55MM; MFG_NAME01: MURATA; MFG_PN01: BLM15HD102SN1; Manufacturer: MURATA; Manufacturer PN: BLM15HD102SN1; ROHS: Yes; Temp Range: -55&#8451; to 125&#8451;
R104 R108 R112 = RES: RES MF 100K 1/16W 1% 0402; AGILE_PN: 470-76240; CAD_APPROVED: Yes; FPLIST: RC0402_25,RC0402_HD,0402_CC; HEIGHT: 0.4MM; MFG_NAME01: NIC COMPONENTS CORP; MFG_PN01: NRCL04F1003TRF; Manufacturer: NIC COMPONENTS CORP; Manufacturer PN: NRCL04F1003TRF; ROHS: Yes; Tolerance: 1%
R168 = RES: RES MF ZERO OHM 1/10W -- 0603; ASSY_OPT: DNP; Assembly Option: DNP; FPLIST: RC0603_OV,RC0603,R603-X2,0603_CC; HEIGHT: 0.6MM; MFG_NAME01: YAGEO AMERICA; MFG_PN01: RC0603FR-070RL; Manufacturer: YAGEO AMERICA; Manufacturer PN: RC0603FR-070RL; ROHS: Yes; Temp Range: –55 °C to +155 °C
R169 = RES: RES MF ZERO OHM 1/10W -- 0603; FPLIST: RC0603_OV,RC0603,R603-X2,0603_CC; HEIGHT: 0.6MM; MFG_NAME01: YAGEO AMERICA; MFG_PN01: RC0603FR-070RL; Manufacturer: YAGEO AMERICA; Manufacturer PN: RC0603FR-070RL; ROHS: Yes; Temp Range: –55 °C to +155 °C
U25-U28 = 74LVCH1T45_6P: IC XCVR XLATING DUAL 3-STATE 1.2- 5.5V TSSOP6; CAD_APPROVED: Yes; Farnell: 3441741; HEIGHT: 1.1MM; MFG_NAME01: NEXPERIA; MFG_PN01: 74AUP1T45GW,125; Manufacturer: NEXPERIA; Manufacturer PN: 74AUP1T45GW,125; Mouser: 771-AUP1T45GW125; ROHS: Yes; VOLTAGE: 1.2- 5.5V; Datasheet: https://assets.nexperia.com/documents/data-sheet/74AUP1T45.pdf

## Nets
3V3: C60.1 C69.1 C70.1 C72.1 C75.1 C76.1 C79.1 C80.1 R88.1 R101.1 R102.1 R169.1 R230.1 U16.3(D) U16.5(VCC) U18.B U20.B U21.16(VCCB) U22.16(VCCB) U24.6(VCCB) U25.1(VCCA) U26.1(VCCA) U27.1(VCCA) U28.1(VCCA) ; also on sheet 5 6
GND: C54.2 C55.2 C60.2 C61.2 C62.2 C63.2 C64.2 C65.2 C66.2 C68.2 C69.2 C70.2 C71.2 C72.2 C73.2 C74.2 C75.2 C76.2 C77.2 C78.2 C79.2 C80.2 C81.2 C88.2 C89.2 C90.1 J35.2 Q8.S(SOURCE) Q10.S(SOURCE) Q11.S(SOURCE) Q16.S(SOURCE) Q17.S(SOURCE) Q21.S(SOURCE) R74.2 R77.1 R81.1 R83.2 R84.1 R106.2 R111.2 R115.2 R168.1 R227.1 U16.2(GND) U17.2(VSS) U18.C U19.4(V-) U20.C U21.2(DIR1) U21.7(DIR4) U21.8(GND1) U21.PAD(NC/GND2) U22.2(DIR1) U22.7(DIR4) U22.8(GND1) U22.15(DIR2) U22.PAD(NC/GND2) U23.3(GND) U24.2(GND) U24.9(E_VSS) U25.2(GND) U26.2(GND) U27.2(GND) U28.2(GND) U30.2(GND) ; also on sheet 1 2 3 4 5 6
P5VA: C54.1 C61.1 C64.1 C65.1 L6.1 R66.2 R72.2 U17.5(VDD) U19.8(V+)
VBUS: C90.2 U30.1(IN) U30.3(EN) ; also on sheet 6
VCC_IF_LINK: C74.1 C77.1 C78.1 C81.1 L7.1 R104.1 R108.1 R112.1 U25.6(VCCB) U26.6(VCCB) U27.6(VCCB) U28.6(VCCB) ; also on sheet 5
ADC0_CH1_CURR: C66.1 J35.1 R82.2 R84.2 TP7.1(TP) U20.E ; also on sheet 5
ADC1_CH1_V: C63.1 R76.2 TP3.1(TP) U18.E ; also on sheet 5
BRG_I2C0_SCL: R101.2 U24.5(SCLB) ; also on sheet 5
BRG_I2C0_SDA: R102.2 U24.4(SDAB) ; also on sheet 5
BRG_SPI1_MISO: U22.12(B3) ; also on sheet 5
BRG_SPI1_MOSI: U22.13(B2) ; also on sheet 5
BRG_SPI1_SCLK: U22.14(B1) ; also on sheet 5
BRG_SPI1_SSEL: U22.11(B4) ; also on sheet 5
CTRL_CAL_DISC: Q21.G(GATE) R227.2 ; also on sheet 5
CTRL_CAL_R1: D20.C ; also on sheet 5
CTRL_CAL_R2: Q17.G(GATE) ; also on sheet 5
CTRL_HIGH_CURR: Q8.G(GATE) Q14.G(GATE) R74.1 U16.4(Q) ; also on sheet 5
CTRL_HIGH_CURR_DIS: U16.6(~{MR}) ; also on sheet 5
CTRL_HIGH_CURR_EN: U16.1(CP) ; also on sheet 5
CURR_SNS+: Q24.S(SOURCE) ; also on sheet 2
CURR_SNS-: Q26.S(SOURCE) ; also on sheet 2
DBGIF_DETECT: R168.2 R169.2 ; also on sheet 5
DBGIF_ISP0_CTRL: R99.2 U23.2(A) ; also on sheet 5
DBGIF_RESET: U27.3(A) ; also on sheet 5
DBGIF_RESET_TXEN: R111.1 U27.5(DIR) ; also on sheet 5
DBGIF_TCK_SWCLK: U26.3(A) ; also on sheet 5
DBGIF_TDO_SWO: U28.3(A) ; also on sheet 5
DBGIF_TMS_SWDIO: U25.3(A) ; also on sheet 5
DBGIF_TMS_SWDIO_TXEN: R106.1 U25.5(DIR) ; also on sheet 5
HW_VER_2: Q11.G(GATE) U24.3(EN) ; also on sheet 5
HW_VER_6: Q10.G(GATE) ; also on sheet 5
HW_VER_7: U26.5(DIR) ; also on sheet 5
MCU_LNK_RX: U21.13(B2) ; also on sheet 5
MCU_LNK_TX: U21.14(B1) ; also on sheet 5
P1_1-MCULINK: R91.1 ; also on sheet 5
P1_9-MCULINK: R88.2 R92.1 ; also on sheet 5
PIO0_0-FC0_CTS_SDA_SSEL0: R97.2 ; also on sheet 2 4
PIO0_2-FC0_RXD_SDA_MOSI: J36.1(A1) R96.2 ; also on sheet 2 3 4
PIO0_3-FC0_TXD_SCL_MISO: J36.3(A2) R95.2 ; also on sheet 2 3 4
PIO0_4-FC0_SCK: R94.2 ; also on sheet 2 4
PIO0_11-SWDCLK: R109.2 ; also on sheet 2
PIO0_12-SWDIO: R105.2 ; also on sheet 2
PIO0_13-FC1_RXD_SDA_MOSI: U24.1(SDAA) ; also on sheet 2 3 4
PIO0_14-FC1_TXD_SCL_MISO: U24.8(SCLA) ; also on sheet 2 3 4
PIO0_17-SWO: R114.2 ; also on sheet 2
PIO0_18-FC2_RXD_SDA_MOSI: J36.5(A3) ; also on sheet 2
PIO0_19-FC2_TXD_SCL_MISO: J36.7(A4) ; also on sheet 2
PIO0_20-ISP: D17.A R100.2 ; also on sheet 2
RDM_RESETn: R110.2 ; also on sheet 2
SYS_5V0: C55.1 L6.2 ; also on sheet 2 6
VIO: C68.1 C71.1 C73.1 L7.2 R93.1 R98.1 R99.1 U21.1(VCCA) U21.15(DIR2) U22.1(VCCA) U22.10(DIR3) U23.5(VCC) U24.7(VCCA) ; also on sheet 2 3 4
N56442: R89.1 U21.4(A2)
N3578794: Q10.D(DRAIN) R93.2 U21.9(~{OE})
N3581084: R87.1 U21.3(A1)
N3594293: Q11.D(DRAIN) R98.2 U22.9(~{OE})
N3596543: R94.1 U22.3(A1)
N3596557: R96.1 U22.4(A2)
N3596571: R95.1 U22.5(A3)
N3596575: R97.1 U22.6(A4)
N4897644: D17.C R90.2
N4898305: R90.1 U21.5(A3)
N4898918: R91.2 U21.12(B3)
N4953028: U21.6(A4) U21.10(DIR3)
N12329989: Q7.S(SOURCE) Q14.D(DRAIN) Q27.S(SOURCE) R67.2 R75.1 R78.1 R224.2 R231.2 TP5.1(TP)
N12329993: C62.1 R75.2 R77.2 U17.3(+IN)
N12330033: R76.1 U17.1(OUT) U17.4(-IN)
N12330403: Q9.S(SOURCE) R83.1 TP6.1(TP) U19.5(+INB)
N12330433: R78.2 U19.2(-INA)
N12330505: C67.2 R82.1 R85.2 U19.7(OUTB)
N12330553: C67.1 R81.2 R85.1 U19.6(-INB)
N12330797: R80.1 U19.1(OUTA)
N12330801: Q9.G(GATE) R80.2
N12330825: Q9.D(DRAIN) R79.2 U19.3(+INA)
N12331089: Q22.D(DRAIN) Q25.S(SOURCE) R73.1 R79.1 R224.1 TP4.1(TP)
N12331509: Q7.D(DRAIN) Q14.S(SOURCE) R73.2
N12333663: Q7.G(GATE) R72.1 R228.1
N12334532: Q8.D(DRAIN) R228.2
N12522256: R115.1 U28.5(DIR)
N12522264: R112.2 R114.1 U28.4(B)
N12522562: R104.2 R105.1 U25.4(B)
N12522860: R108.2 R110.1 U27.4(B)
N12527022: R109.1 U26.4(B)
N12533780: R100.1 U23.4(Y)
N12537164: R92.2 U21.11(B4)
N12790182: C88.1 Q20.D(DRAIN) U30.5(OUT)
N12790214: C89.1 U30.4(NC)
N12795272: Q16.D(DRAIN) R67.1
N12795276: Q17.D(DRAIN) R71.1
N12795416: D20.A Q16.G(GATE) R230.2
N12796249: Q20.S(SOURCE) Q22.S(SOURCE)
N12796253: Q20.G(GATE) Q21.D(DRAIN) Q22.G(GATE) Q24.G(GATE) Q25.G(GATE) Q26.G(GATE) Q27.G(GATE) R66.1
N12796853: Q24.D(DRAIN) Q25.D(DRAIN)
N12797165: Q26.D(DRAIN) Q27.D(DRAIN)
N12815289: J36.4(B2) J36.8(B4) R89.2
N12815293: J36.2(B1) J36.6(B3) R87.2
N12901647: R71.2 R231.1

Not connected (* = marked no-connect by the designer): U23 1(NC)*

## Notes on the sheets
sheet 7
- Rs
  (LOW CURR)
  0 ~ 1mA range
- Limit voltage drop over Rs to 50mV
  Fast switch to low ohm Rs
- Rs
  (HIGH CURR)
  0 ~ 50mA range
- CTRL_HIGH_CURR_DIS shall go low when voltage
  over Rs exceed 50mV (adj)
- Note: Bleeding reistors
  @3.0V: bleeding will be 4.5µA
  @1.2V: bleeding will be 1.8µA
- Ra
- Rb
- Rd
- V= I*Rs*Rb/Ra*(1+Rc/Rd)
  Rs = 200R ==> Vout = 600mV/µA
  Rs = 2R ==> Vout = 60mV/mA
  BW = 250kHz
- V= I*Rs*Rb/Ra
  Rs = 200R ==> Vout = 1V/mA
  Rs = 2R ==> Vout = 20mV/mA
- Rc
sheet 8
- Voltage Translation
  Buffers
- Target MCXW23x
- Debugger MCU
- DIR#  L: B to A
  H: A to B
- DBGIF_ISP0_CTRL configured as OC on LPC55S69
- Target Side
- Debugger Side
- Slave
- Master
- DIR#  L: B to A
  H: A to B
sheet 9
- DIR#  L: B to A, H: A to B
- DIR#  L: B to A, H: A to B
- DIR#  L: B to A, H: A to B
- DIR#  L: B to A, H: A to B
- DIR#  L: B to A, H: A to B
